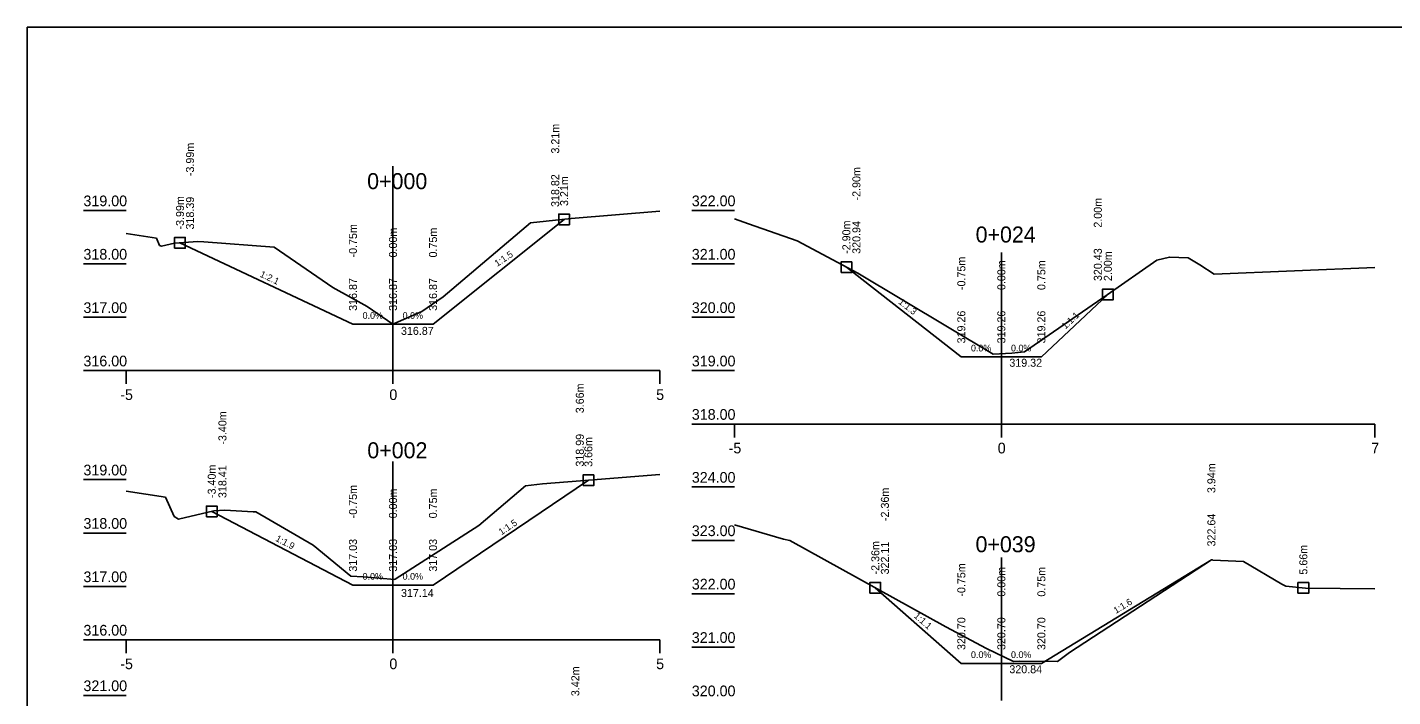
# Model space of a CAD drawing. Extents: x -558995.4 to -558953.4, y -1164517.9 to -1164488.2.
# Drawn here: x -558995.41 to -558969.83, y -1164500.72 to -1164488.18 of the extents above; entities that cross this region are included whole.
import ezdxf

# ---------------------------------------------------------------- set-up
doc = ezdxf.new("R2010")
doc.units = 0
for name, color, linetype in [('16', 7, 'Continuous'), ('21', 7, 'Continuous'), ('28', 7, 'Continuous'), ('59', 7, 'Continuous'), ('Body pricny rez', 7, 'Continuous'), ('Hranice_pozemku', 7, 'Continuous'), ('Popis pricneho profilu', 7, 'Continuous')]:
    doc.layers.add(name, color=color, linetype=linetype)

msp = doc.modelspace()

# ---------------------------------------------------------------- linework, layer by layer
for p, q in [((-558953.413, -1164488.18), (-558995.413, -1164488.18)), ((-558995.413, -1164488.18), (-558995.413, -1164517.88))]:
    msp.add_line(p, q)
for points in [[(-558993.561, -1164492.042), (-558992.995, -1164492.127), (-558992.934, -1164492.264), (-558992.901, -1164492.282), (-558992.652, -1164492.224), (-558992.216, -1164492.19), (-558992.103, -1164492.197), (-558990.788, -1164492.295), (-558989.69, -1164493.055), (-558989.043, -1164493.407), (-558988.561, -1164493.741), (-558988.019, -1164493.502), (-558987.623, -1164493.231), (-558985.985, -1164491.842), (-558985.223, -1164491.764), (-558983.561, -1164491.626)], [(-558992.552, -1164492.217), (-558989.311, -1164493.741), (-558988.561, -1164493.741), (-558987.811, -1164493.741), (-558985.354, -1164491.777)], [(-558987.811, -1164493.741), (-558985.354, -1164491.777)], [(-558982.161, -1164491.766), (-558981.898, -1164491.86), (-558980.988, -1164492.178), (-558979.852, -1164492.788), (-558977.317, -1164494.304), (-558976.964, -1164494.283), (-558976.726, -1164494.261), (-558975.177, -1164493.192), (-558974.248, -1164492.543), (-558974.013, -1164492.484), (-558973.658, -1164492.5), (-558973.444, -1164492.626), (-558973.171, -1164492.806), (-558970.161, -1164492.677)], [(-558989.311, -1164493.741), (-558992.552, -1164492.217)], [(-558980.065, -1164492.673), (-558977.911, -1164494.351), (-558977.161, -1164494.351), (-558976.411, -1164494.351), (-558975.165, -1164493.183)], [(-558977.911, -1164494.351), (-558980.065, -1164492.673)], [(-558976.411, -1164494.351), (-558975.165, -1164493.183)], [(-558988.561, -1164493.741), (-558989.311, -1164493.741)], [(-558988.561, -1164493.741), (-558987.811, -1164493.741)], [(-558977.161, -1164494.351), (-558977.911, -1164494.351)], [(-558977.161, -1164494.351), (-558976.411, -1164494.351)], [(-558993.561, -1164496.871), (-558992.825, -1164496.983), (-558992.663, -1164497.343), (-558992.579, -1164497.39), (-558991.921, -1164497.239), (-558991.709, -1164497.222), (-558991.18, -1164497.256), (-558991.134, -1164497.256), (-558990.057, -1164497.883), (-558989.35, -1164498.46), (-558989.119, -1164498.472), (-558989.113, -1164498.472), (-558988.525, -1164498.521), (-558988.521, -1164498.516), (-558986.953, -1164497.509), (-558986.076, -1164496.766), (-558985.762, -1164496.733), (-558985.05, -1164496.674), (-558983.561, -1164496.558)], [(-558987.811, -1164498.627), (-558984.9, -1164496.663)], [(-558989.311, -1164498.627), (-558991.957, -1164497.247)], [(-558982.161, -1164497.496), (-558981.24, -1164497.765), (-558981.126, -1164497.792), (-558978.199, -1164499.41), (-558977.438, -1164499.814), (-558976.936, -1164500.062), (-558976.821, -1164500.055), (-558976.109, -1164500.056), (-558975.881, -1164499.892), (-558973.225, -1164498.154), (-558973.206, -1164498.157), (-558973.197, -1164498.158), (-558972.621, -1164498.183), (-558971.908, -1164498.612), (-558971.827, -1164498.648), (-558971.463, -1164498.686), (-558970.161, -1164498.698)], [(-558976.411, -1164500.094), (-558973.225, -1164498.154)], [(-558988.561, -1164498.627), (-558989.311, -1164498.627)], [(-558988.561, -1164498.627), (-558987.811, -1164498.627)], [(-558977.911, -1164500.094), (-558979.523, -1164498.678)], [(-558977.161, -1164500.094), (-558977.911, -1164500.094)], [(-558977.161, -1164500.094), (-558976.411, -1164500.094)]]:
    msp.add_lwpolyline(points)
at = {"layer": '16'}
for p, q in [((-558993.561, -1164494.611), (-558983.561, -1164494.611)), ((-558982.161, -1164495.611), (-558970.161, -1164495.611)), ((-558993.561, -1164499.653), (-558983.561, -1164499.653))]:
    msp.add_line(p, q, dxfattribs=at)
at = {"layer": '21'}
for p, q in [((-558994.361, -1164491.611), (-558993.561, -1164491.611)), ((-558982.961, -1164491.611), (-558982.161, -1164491.611)), ((-558994.361, -1164492.611), (-558993.561, -1164492.611)), ((-558982.961, -1164492.611), (-558982.161, -1164492.611)), ((-558994.361, -1164493.611), (-558993.561, -1164493.611)), ((-558982.961, -1164493.611), (-558982.161, -1164493.611)), ((-558994.361, -1164494.611), (-558993.561, -1164494.611)), ((-558982.961, -1164494.611), (-558982.161, -1164494.611)), ((-558982.961, -1164495.611), (-558982.161, -1164495.611)), ((-558994.361, -1164496.653), (-558993.561, -1164496.653)), ((-558982.961, -1164496.79), (-558982.161, -1164496.79)), ((-558994.361, -1164497.653), (-558993.561, -1164497.653)), ((-558982.961, -1164497.79), (-558982.161, -1164497.79)), ((-558994.361, -1164498.653), (-558993.561, -1164498.653)), ((-558982.961, -1164498.79), (-558982.161, -1164498.79)), ((-558994.361, -1164499.653), (-558993.561, -1164499.653)), ((-558982.961, -1164499.79), (-558982.161, -1164499.79)), ((-558994.361, -1164500.694), (-558993.561, -1164500.694))]:
    msp.add_line(p, q, dxfattribs=at)
at = {"layer": '28'}
for p, q in [((-558988.561, -1164490.782), (-558988.561, -1164494.611)), ((-558977.161, -1164492.401), (-558977.161, -1164495.611)), ((-558988.561, -1164496.312), (-558988.561, -1164499.653)), ((-558977.161, -1164498.112), (-558977.161, -1164500.79))]:
    msp.add_line(p, q, dxfattribs=at)
at = {"layer": '59'}
for p, q in [((-558993.561, -1164494.861), (-558993.561, -1164494.611)), ((-558988.561, -1164494.861), (-558988.561, -1164494.611)), ((-558983.561, -1164494.861), (-558983.561, -1164494.611)), ((-558982.161, -1164495.861), (-558982.161, -1164495.611)), ((-558977.161, -1164495.861), (-558977.161, -1164495.611)), ((-558970.161, -1164495.861), (-558970.161, -1164495.611)), ((-558993.561, -1164499.903), (-558993.561, -1164499.653)), ((-558988.561, -1164499.903), (-558988.561, -1164499.653)), ((-558983.561, -1164499.903), (-558983.561, -1164499.653))]:
    msp.add_line(p, q, dxfattribs=at)
at = {"layer": 'Hranice_pozemku'}
for points in [[(-558985.454, -1164491.877), (-558985.254, -1164491.877), (-558985.254, -1164491.677), (-558985.454, -1164491.677)], [(-558992.652, -1164492.317), (-558992.452, -1164492.317), (-558992.452, -1164492.117), (-558992.652, -1164492.117)], [(-558980.165, -1164492.773), (-558979.965, -1164492.773), (-558979.965, -1164492.573), (-558980.165, -1164492.573)], [(-558975.265, -1164493.283), (-558975.065, -1164493.283), (-558975.065, -1164493.083), (-558975.265, -1164493.083)], [(-558985, -1164496.763), (-558984.8, -1164496.763), (-558984.8, -1164496.563), (-558985, -1164496.563)], [(-558992.057, -1164497.347), (-558991.857, -1164497.347), (-558991.857, -1164497.147), (-558992.057, -1164497.147)], [(-558979.623, -1164498.778), (-558979.423, -1164498.778), (-558979.423, -1164498.578), (-558979.623, -1164498.578)], [(-558971.602, -1164498.782), (-558971.402, -1164498.782), (-558971.402, -1164498.582), (-558971.602, -1164498.582)]]:
    msp.add_lwpolyline(points, close=True, dxfattribs=at)

# ---------------------------------------------------------------- texts
for s, p in [('0+000', (-558989.045, -1164491.211)), ('0+024', (-558977.643, -1164492.211)), ('0+002', (-558989.042, -1164496.253)), ('0+039', (-558977.645, -1164498.013))]:
    msp.add_text(s, height=0.3).set_placement(p)
for s, rotation, p in [('1:1.5', 33.6901, (-558986.607, -1164492.668)), ('1:2.1', 334.8067, (-558991.066, -1164492.847)), ('1:1.3', 322.0829, (-558979.1, -1164493.346)), ('1:1.1', 43.1215, (-558975.961, -1164493.843)), ('1:1.5', 33.6901, (-558986.529, -1164497.697)), ('1:1.9', 332.4443, (-558990.774, -1164497.794)), ('1:1.6', 31.3335, (-558975.013, -1164499.169)), ('1:1.1', 318.7016, (-558978.81, -1164499.222))]:
    msp.add_text(s, height=0.125, rotation=rotation).set_placement(p)
at = {"layer": '16'}
for p in [(-558989.13, -1164493.641), (-558988.38, -1164493.641), (-558977.73, -1164494.251), (-558976.98, -1164494.251), (-558989.13, -1164498.527), (-558988.38, -1164498.527), (-558977.73, -1164499.994), (-558976.98, -1164499.994)]:
    msp.add_text('0.0%', height=0.125, dxfattribs=at).set_placement(p)
at = {"layer": '21'}
for s, p in [('319.00', (-558994.361, -1164491.531)), ('322.00', (-558982.961, -1164491.531)), ('318.00', (-558994.361, -1164492.531)), ('321.00', (-558982.961, -1164492.531)), ('317.00', (-558994.361, -1164493.531)), ('320.00', (-558982.961, -1164493.531)), ('316.00', (-558994.361, -1164494.531)), ('319.00', (-558982.961, -1164494.531)), ('-5', (-558993.672, -1164495.161)), ('0', (-558988.629, -1164495.161)), ('5', (-558983.629, -1164495.161)), ('318.00', (-558982.961, -1164495.531)), ('-5', (-558982.272, -1164496.161)), ('0', (-558977.229, -1164496.161)), ('7', (-558970.229, -1164496.161)), ('319.00', (-558994.361, -1164496.573)), ('324.00', (-558982.961, -1164496.71)), ('318.00', (-558994.361, -1164497.573)), ('323.00', (-558982.961, -1164497.71)), ('317.00', (-558994.361, -1164498.573)), ('322.00', (-558982.961, -1164498.71)), ('316.00', (-558994.361, -1164499.573)), ('321.00', (-558982.961, -1164499.71)), ('-5', (-558993.672, -1164500.203)), ('0', (-558988.629, -1164500.203)), ('5', (-558983.629, -1164500.203)), ('321.00', (-558994.361, -1164500.614)), ('320.00', (-558982.961, -1164500.71))]:
    msp.add_text(s, height=0.2, dxfattribs=at).set_placement(p)
at = {"layer": '59'}
for s, p in [('316.87', (-558988.411, -1164493.941)), ('316.87', (-558988.411, -1164493.941)), ('319.32', (-558977.011, -1164494.538)), ('319.32', (-558977.011, -1164494.538)), ('317.14', (-558988.411, -1164498.851)), ('317.14', (-558988.411, -1164498.851)), ('320.84', (-558977.011, -1164500.279)), ('320.84', (-558977.011, -1164500.279))]:
    msp.add_text(s, height=0.15, dxfattribs=at).set_placement(p)
at = {"layer": 'Body pricny rez'}
for p in [(-558984.792, -1164491.729), (-558992.553, -1164492.217), (-558980.066, -1164492.674), (-558975.165, -1164493.184), (-558989.312, -1164493.742), (-558988.562, -1164493.742), (-558987.812, -1164493.742), (-558977.912, -1164494.351), (-558977.162, -1164494.351), (-558976.412, -1164494.351), (-558984.86, -1164496.66), (-558991.958, -1164497.247), (-558973.226, -1164498.154), (-558989.312, -1164498.628), (-558988.562, -1164498.628), (-558987.812, -1164498.628), (-558979.523, -1164498.679), (-558977.912, -1164500.094), (-558977.162, -1164500.094), (-558976.412, -1164500.094)]:
    msp.add_text('+', height=0.001, dxfattribs=at).set_placement(p)
at = {"layer": 'Popis pricneho profilu'}
for s, p in [('3.21m', (-558985.446, -1164490.545)), ('-3.99m', (-558992.289, -1164490.967)), ('318.82', (-558985.446, -1164491.545)), ('3.21m', (-558985.279, -1164491.527)), ('-2.90m', (-558979.802, -1164491.423)), ('-3.99m', (-558992.477, -1164491.967)), ('318.39', (-558992.289, -1164491.967)), ('2.00m', (-558975.278, -1164491.933)), ('-0.75m', (-558989.236, -1164492.491)), ('0.00m', (-558988.486, -1164492.491)), ('0.75m', (-558987.736, -1164492.491)), ('-2.90m', (-558979.99, -1164492.423)), ('320.94', (-558979.802, -1164492.423)), ('-0.75m', (-558977.836, -1164493.101)), ('0.00m', (-558977.086, -1164493.101)), ('0.75m', (-558976.336, -1164493.101)), ('320.43', (-558975.278, -1164492.933)), ('2.00m', (-558975.09, -1164492.933)), ('316.87', (-558989.236, -1164493.491)), ('316.87', (-558988.486, -1164493.491)), ('316.87', (-558987.736, -1164493.491)), ('319.26', (-558977.836, -1164494.101)), ('319.26', (-558977.086, -1164494.101)), ('319.26', (-558976.336, -1164494.101)), ('3.66m', (-558984.985, -1164495.409)), ('-3.40m', (-558991.682, -1164495.997)), ('318.99', (-558984.985, -1164496.409)), ('3.66m', (-558984.825, -1164496.413)), ('-3.40m', (-558991.882, -1164496.997)), ('318.41', (-558991.682, -1164496.997)), ('3.94m', (-558973.15, -1164496.904)), ('-0.75m', (-558989.236, -1164497.377)), ('0.00m', (-558988.486, -1164497.377)), ('0.75m', (-558987.736, -1164497.377)), ('-2.36m', (-558979.268, -1164497.428)), ('322.64', (-558973.15, -1164497.904)), ('317.03', (-558989.236, -1164498.377)), ('317.03', (-558988.486, -1164498.377)), ('317.03', (-558987.736, -1164498.377)), ('-2.36m', (-558979.448, -1164498.428)), ('322.11', (-558979.268, -1164498.428)), ('5.66m', (-558971.427, -1164498.432)), ('-0.75m', (-558977.836, -1164498.844)), ('0.00m', (-558977.086, -1164498.844)), ('0.75m', (-558976.336, -1164498.844)), ('320.70', (-558977.836, -1164499.844)), ('320.70', (-558977.086, -1164499.844)), ('320.70', (-558976.336, -1164499.844)), ('3.42m', (-558985.069, -1164500.708))]:
    msp.add_text(s, height=0.15, rotation=90, dxfattribs=at).set_placement(p)

doc.saveas('drawing.dxf')
